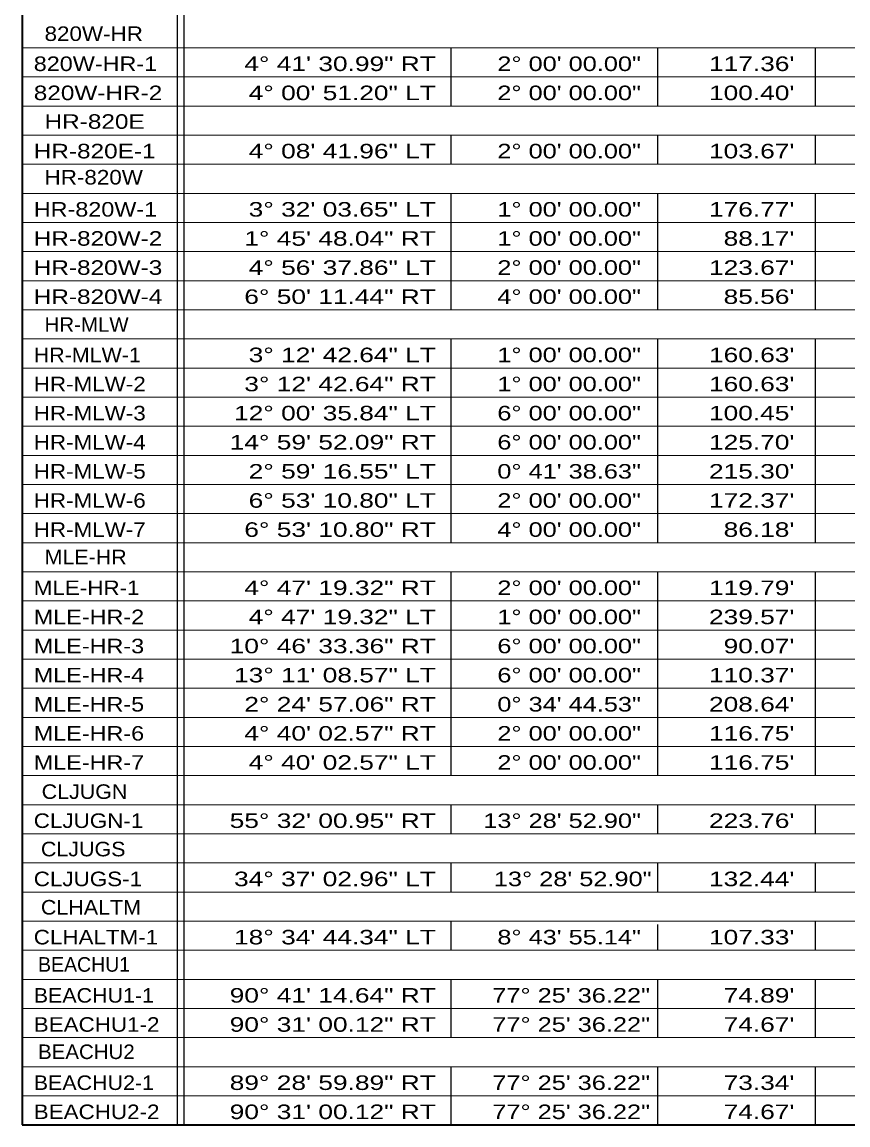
# Model space of a CAD drawing. Extents: x 1953053 to 1967065, y 7363860 to 7371201.
# Drawn here: x 1957927 to 1958608, y 7368424 to 7369333 of the extents above; entities that cross this region are included whole.
import ezdxf
from ezdxf.enums import TextEntityAlignment as Align

# ---------------------------------------------------------------- set-up
doc = ezdxf.new("R2010")
doc.units = 0
doc.header["$LTSCALE"] = 4.8
doc.layers.add('10', color=7, linetype='Continuous')
doc.layers.add('12', color=7, linetype='Continuous', lineweight=25)

msp = doc.modelspace()

# ---------------------------------------------------------------- linework, layer by layer
at = {"layer": '12', "lineweight": 35}
for p, q in [((1957927.305, 7370164.879), (1957927.305, 7368423.747)), ((1957927.305, 7368423.747), (1959650.637, 7368423.747))]:
    msp.add_line(p, q, dxfattribs=at)
at = {"layer": '12'}
for p, q in [((1958055.15, 7370136.079), (1958055.15, 7368423.747)), ((1958060.637, 7370136.079), (1958060.637, 7368423.747)), ((1958280.637, 7369311.746), (1958280.637, 7369263.746)), ((1958450.637, 7369311.746), (1958450.637, 7369263.746)), ((1958580.637, 7369311.746), (1958580.637, 7369263.746)), ((1958280.637, 7369239.746), (1958280.637, 7369215.746)), ((1958450.637, 7369239.746), (1958450.637, 7369215.746)), ((1958580.637, 7369239.746), (1958580.637, 7369215.746)), ((1958280.637, 7369191.746), (1958280.637, 7369095.746)), ((1958450.637, 7369191.746), (1958450.637, 7369095.746)), ((1958580.637, 7369191.746), (1958580.637, 7369095.746)), ((1958280.637, 7369071.746), (1958280.637, 7368903.747)), ((1958450.637, 7369071.746), (1958450.637, 7368903.747)), ((1958580.637, 7369071.746), (1958580.637, 7368903.747)), ((1958280.637, 7368879.747), (1958280.637, 7368711.747)), ((1958450.637, 7368879.747), (1958450.637, 7368711.747)), ((1958580.637, 7368879.747), (1958580.637, 7368711.747)), ((1958280.637, 7368687.747), (1958280.637, 7368663.747)), ((1958450.637, 7368687.747), (1958450.637, 7368663.747)), ((1958580.637, 7368687.747), (1958580.637, 7368663.747)), ((1958280.637, 7368639.747), (1958280.637, 7368615.747)), ((1958450.637, 7368639.747), (1958450.637, 7368615.747)), ((1958580.637, 7368639.747), (1958580.637, 7368615.747)), ((1958280.637, 7368591.293), (1958280.637, 7368567.747)), ((1958580.637, 7368591.747), (1958580.637, 7368567.747)), ((1958450.637, 7368589.107), (1958450.637, 7368567.747)), ((1958280.637, 7368543.747), (1958280.637, 7368495.747)), ((1958450.637, 7368543.747), (1958450.637, 7368495.747)), ((1958580.637, 7368543.747), (1958580.637, 7368495.747)), ((1958280.637, 7368471.747), (1958280.637, 7368423.747)), ((1958450.637, 7368471.747), (1958450.637, 7368423.747)), ((1958580.637, 7368471.747), (1958580.637, 7368423.747))]:
    msp.add_line(p, q, dxfattribs=at)
at = {"layer": '12', "lineweight": 13}
for p, q in [((1957927.305, 7369311.746), (1959650.637, 7369311.746)), ((1957927.305, 7369287.746), (1959650.637, 7369287.746)), ((1957927.305, 7369263.746), (1959650.637, 7369263.746)), ((1957927.305, 7369239.746), (1959650.637, 7369239.746)), ((1957927.305, 7369215.746), (1959650.637, 7369215.746)), ((1957927.305, 7369191.746), (1959650.637, 7369191.746)), ((1957927.305, 7369167.746), (1959650.637, 7369167.746)), ((1957927.305, 7369143.746), (1959650.637, 7369143.746)), ((1957927.305, 7369119.746), (1959650.637, 7369119.746)), ((1957927.305, 7369095.746), (1959650.637, 7369095.746)), ((1957927.305, 7369071.746), (1959650.637, 7369071.746)), ((1957927.305, 7369047.746), (1959650.637, 7369047.746)), ((1957927.305, 7369023.746), (1959650.637, 7369023.746)), ((1957927.305, 7368999.746), (1959650.637, 7368999.746)), ((1957927.305, 7368975.747), (1959650.637, 7368975.747)), ((1957927.305, 7368951.747), (1959650.637, 7368951.747)), ((1957927.305, 7368927.747), (1959650.637, 7368927.747)), ((1957927.305, 7368903.747), (1959650.637, 7368903.747)), ((1957927.305, 7368879.747), (1959650.637, 7368879.747)), ((1957927.305, 7368855.747), (1959650.637, 7368855.747)), ((1957927.305, 7368831.747), (1959650.637, 7368831.747)), ((1957927.305, 7368807.747), (1959650.637, 7368807.747)), ((1957927.305, 7368783.747), (1959650.637, 7368783.747)), ((1957927.305, 7368759.747), (1959650.637, 7368759.747)), ((1957927.305, 7368735.747), (1959650.637, 7368735.747)), ((1957927.305, 7368711.747), (1959650.637, 7368711.747)), ((1957927.305, 7368687.747), (1959650.637, 7368687.747)), ((1957927.305, 7368663.747), (1959650.637, 7368663.747)), ((1957927.305, 7368663.747), (1959650.637, 7368663.747)), ((1957927.305, 7368639.747), (1959650.637, 7368639.747)), ((1957927.305, 7368615.747), (1959650.637, 7368615.747)), ((1957927.305, 7368591.747), (1959650.637, 7368591.747)), ((1957927.305, 7368567.747), (1959650.637, 7368567.747)), ((1957927.305, 7368567.747), (1959650.637, 7368567.747)), ((1957927.305, 7368543.747), (1959650.637, 7368543.747)), ((1957927.305, 7368519.747), (1959650.637, 7368519.747)), ((1957927.305, 7368495.747), (1959650.637, 7368495.747)), ((1957927.305, 7368471.747), (1959650.637, 7368471.747)), ((1957927.305, 7368447.747), (1959650.637, 7368447.747))]:
    msp.add_line(p, q, dxfattribs=at)

# ---------------------------------------------------------------- texts
at = {"layer": '10'}
for s, width, p in [('820W-HR', 1.15, (1957945.832, 7369317.374)), ('820W-HR-1', 1.2, (1957936.926, 7369292.573)), ('820W-HR-2', 1.25, (1957936.926, 7369268.573)), ('HR-820E', 1.25, (1957945.832, 7369244.963)), ('HR-820E-1', 1.25, (1957936.926, 7369220.573)), ('HR-820W', 1.15, (1957945.832, 7369199.044)), ('HR-820W-1', 1.2, (1957936.926, 7369172.573)), ('HR-820W-2', 1.25, (1957936.926, 7369148.573)), ('HR-820W-3', 1.25, (1957936.926, 7369124.573)), ('HR-820W-4', 1.25, (1957936.926, 7369100.573)), ('HR-MLW', 1.05, (1957945.832, 7369077.592)), ('HR-MLW-1', 1.1, (1957936.926, 7369052.573)), ('HR-MLW-2', 1.15, (1957936.926, 7369028.573)), ('HR-MLW-3', 1.15, (1957936.926, 7369004.573)), ('HR-MLW-4', 1.15, (1957936.926, 7368980.573)), ('HR-MLW-5', 1.15, (1957936.926, 7368956.573)), ('HR-MLW-6', 1.15, (1957936.926, 7368932.573)), ('HR-MLW-7', 1.15, (1957936.926, 7368908.573)), ('MLE-HR', 1.1, (1957945.832, 7368885.969)), ('MLE-HR-1', 1.15, (1957936.926, 7368860.574)), ('MLE-HR-2', 1.2, (1957936.926, 7368836.574)), ('MLE-HR-3', 1.2, (1957936.926, 7368812.574)), ('MLE-HR-4', 1.2, (1957936.926, 7368788.574)), ('MLE-HR-5', 1.2, (1957936.926, 7368764.574)), ('MLE-HR-6', 1.2, (1957936.926, 7368740.574)), ('MLE-HR-7', 1.2, (1957936.926, 7368716.574)), ('CLJUGN', 1.1, (1957943.437, 7368692.533)), ('CLJUGN-1', 1.15, (1957936.926, 7368668.574)), ('CLJUGS', 1.1, (1957942.838, 7368645.192)), ('CLJUGS-1', 1.15, (1957936.926, 7368620.574)), ('CLHALTM', 1.1, (1957942.838, 7368597.192)), ('CLHALTM-1', 1.15, (1957936.926, 7368572.574)), ('BEACHU1-1', 1.1, (1957936.926, 7368524.574)), ('BEACHU1-2', 1.15, (1957936.926, 7368500.574)), ('BEACHU2', 1.05, (1957940.49, 7368478.077)), ('BEACHU2-1', 1.1, (1957936.926, 7368452.574)), ('BEACHU2-2', 1.15, (1957936.926, 7368428.574))]:
    msp.add_text(s, height=12, dxfattribs=dict(at, width=width)).set_placement(p)
for s, width, p in [('4° 41\' 30.99" RT', 1.35, (1958268.159, 7369292.573)), ('2° 00\' 00.00"', 1.3, (1958437.154, 7369292.573)), ("117.36'", 1.35, (1958563.564, 7369292.573)), ('4° 00\' 51.20" LT', 1.35, (1958268.159, 7369268.573)), ('2° 00\' 00.00"', 1.3, (1958437.154, 7369268.573)), ("100.40'", 1.35, (1958563.564, 7369268.573)), ('4° 08\' 41.96" LT', 1.35, (1958268.159, 7369220.573)), ('2° 00\' 00.00"', 1.3, (1958437.154, 7369220.573)), ("103.67'", 1.35, (1958563.564, 7369220.573)), ('3° 32\' 03.65" LT', 1.35, (1958268.159, 7369172.573)), ('1° 00\' 00.00"', 1.3, (1958437.154, 7369172.573)), ("176.77'", 1.35, (1958563.564, 7369172.573)), ('1° 45\' 48.04" RT', 1.35, (1958268.159, 7369148.573)), ('1° 00\' 00.00"', 1.3, (1958437.154, 7369148.573)), ("88.17'", 1.35, (1958563.564, 7369148.573)), ('4° 56\' 37.86" LT', 1.35, (1958268.159, 7369124.573)), ('2° 00\' 00.00"', 1.3, (1958437.154, 7369124.573)), ("123.67'", 1.35, (1958563.564, 7369124.573)), ('6° 50\' 11.44" RT', 1.35, (1958268.159, 7369100.573)), ('4° 00\' 00.00"', 1.3, (1958437.154, 7369100.573)), ("85.56'", 1.35, (1958563.564, 7369100.573)), ('3° 12\' 42.64" LT', 1.35, (1958268.159, 7369052.573)), ('1° 00\' 00.00"', 1.3, (1958437.154, 7369052.573)), ("160.63'", 1.35, (1958563.564, 7369052.573)), ('3° 12\' 42.64" RT', 1.35, (1958268.159, 7369028.573)), ('1° 00\' 00.00"', 1.3, (1958437.154, 7369028.573)), ("160.63'", 1.35, (1958563.564, 7369028.573)), ('12° 00\' 35.84" LT', 1.35, (1958268.159, 7369004.573)), ('6° 00\' 00.00"', 1.3, (1958437.154, 7369004.573)), ("100.45'", 1.35, (1958563.564, 7369004.573)), ('14° 59\' 52.09" RT', 1.35, (1958268.159, 7368980.573)), ('6° 00\' 00.00"', 1.3, (1958437.154, 7368980.573)), ("125.70'", 1.35, (1958563.564, 7368980.573)), ('2° 59\' 16.55" LT', 1.35, (1958268.159, 7368956.573)), ('0° 41\' 38.63"', 1.3, (1958437.154, 7368956.573)), ("215.30'", 1.35, (1958563.564, 7368956.573)), ('6° 53\' 10.80" LT', 1.35, (1958268.159, 7368932.573)), ('2° 00\' 00.00"', 1.3, (1958437.154, 7368932.573)), ("172.37'", 1.35, (1958563.564, 7368932.573)), ('6° 53\' 10.80" RT', 1.35, (1958268.159, 7368908.573)), ('4° 00\' 00.00"', 1.3, (1958437.154, 7368908.573)), ("86.18'", 1.35, (1958563.564, 7368908.573)), ('4° 47\' 19.32" RT', 1.35, (1958268.159, 7368860.574)), ('2° 00\' 00.00"', 1.3, (1958437.154, 7368860.574)), ("119.79'", 1.35, (1958563.564, 7368860.574)), ('4° 47\' 19.32" LT', 1.35, (1958268.159, 7368836.574)), ('1° 00\' 00.00"', 1.3, (1958437.154, 7368836.574)), ("239.57'", 1.35, (1958563.564, 7368836.574)), ('10° 46\' 33.36" RT', 1.35, (1958268.159, 7368812.574)), ('6° 00\' 00.00"', 1.3, (1958437.154, 7368812.574)), ("90.07'", 1.35, (1958563.564, 7368812.574)), ('13° 11\' 08.57" LT', 1.35, (1958268.159, 7368788.574)), ('6° 00\' 00.00"', 1.3, (1958437.154, 7368788.574)), ("110.37'", 1.35, (1958563.564, 7368788.574)), ('2° 24\' 57.06" RT', 1.35, (1958268.159, 7368764.574)), ('0° 34\' 44.53"', 1.3, (1958437.154, 7368764.574)), ("208.64'", 1.35, (1958563.564, 7368764.574)), ('4° 40\' 02.57" RT', 1.35, (1958268.159, 7368740.574)), ('2° 00\' 00.00"', 1.3, (1958437.154, 7368740.574)), ("116.75'", 1.35, (1958563.564, 7368740.574)), ('4° 40\' 02.57" LT', 1.35, (1958268.159, 7368716.574)), ('2° 00\' 00.00"', 1.3, (1958437.154, 7368716.574)), ("116.75'", 1.35, (1958563.564, 7368716.574)), ('55° 32\' 00.95" RT', 1.35, (1958268.159, 7368668.574)), ('13° 28\' 52.90"', 1.3, (1958437.154, 7368668.574)), ("223.76'", 1.35, (1958563.564, 7368668.574)), ('34° 37\' 02.96" LT', 1.35, (1958268.159, 7368620.574)), ('13° 28\' 52.90"', 1.3, (1958445.909, 7368620.574)), ("132.44'", 1.35, (1958563.564, 7368620.574)), ('18° 34\' 44.34" LT', 1.35, (1958268.159, 7368572.574)), ('8° 43\' 55.14"', 1.3, (1958437.154, 7368572.574)), ("107.33'", 1.35, (1958563.564, 7368572.574)), ('90° 41\' 14.64" RT', 1.35, (1958268.159, 7368524.574)), ('77° 25\' 36.22"', 1.3, (1958444.624, 7368524.574)), ("74.89'", 1.35, (1958563.564, 7368524.574)), ('90° 31\' 00.12" RT', 1.35, (1958268.159, 7368500.574)), ('77° 25\' 36.22"', 1.3, (1958444.624, 7368500.574)), ("74.67'", 1.35, (1958563.564, 7368500.574)), ('89° 28\' 59.89" RT', 1.35, (1958268.159, 7368452.574)), ('77° 25\' 36.22"', 1.3, (1958444.624, 7368452.574)), ("73.34'", 1.35, (1958563.564, 7368452.574)), ('90° 31\' 00.12" RT', 1.35, (1958268.159, 7368428.574)), ('77° 25\' 36.22"', 1.3, (1958444.624, 7368428.574)), ("74.67'", 1.35, (1958563.564, 7368428.574))]:
    msp.add_text(s, height=12, dxfattribs=dict(at, width=width)).set_placement(p, align=Align.RIGHT)
msp.add_text('BEACHU1', height=12, dxfattribs=at).set_placement((1957940.49, 7368550.077))

doc.saveas('drawing.dxf')
